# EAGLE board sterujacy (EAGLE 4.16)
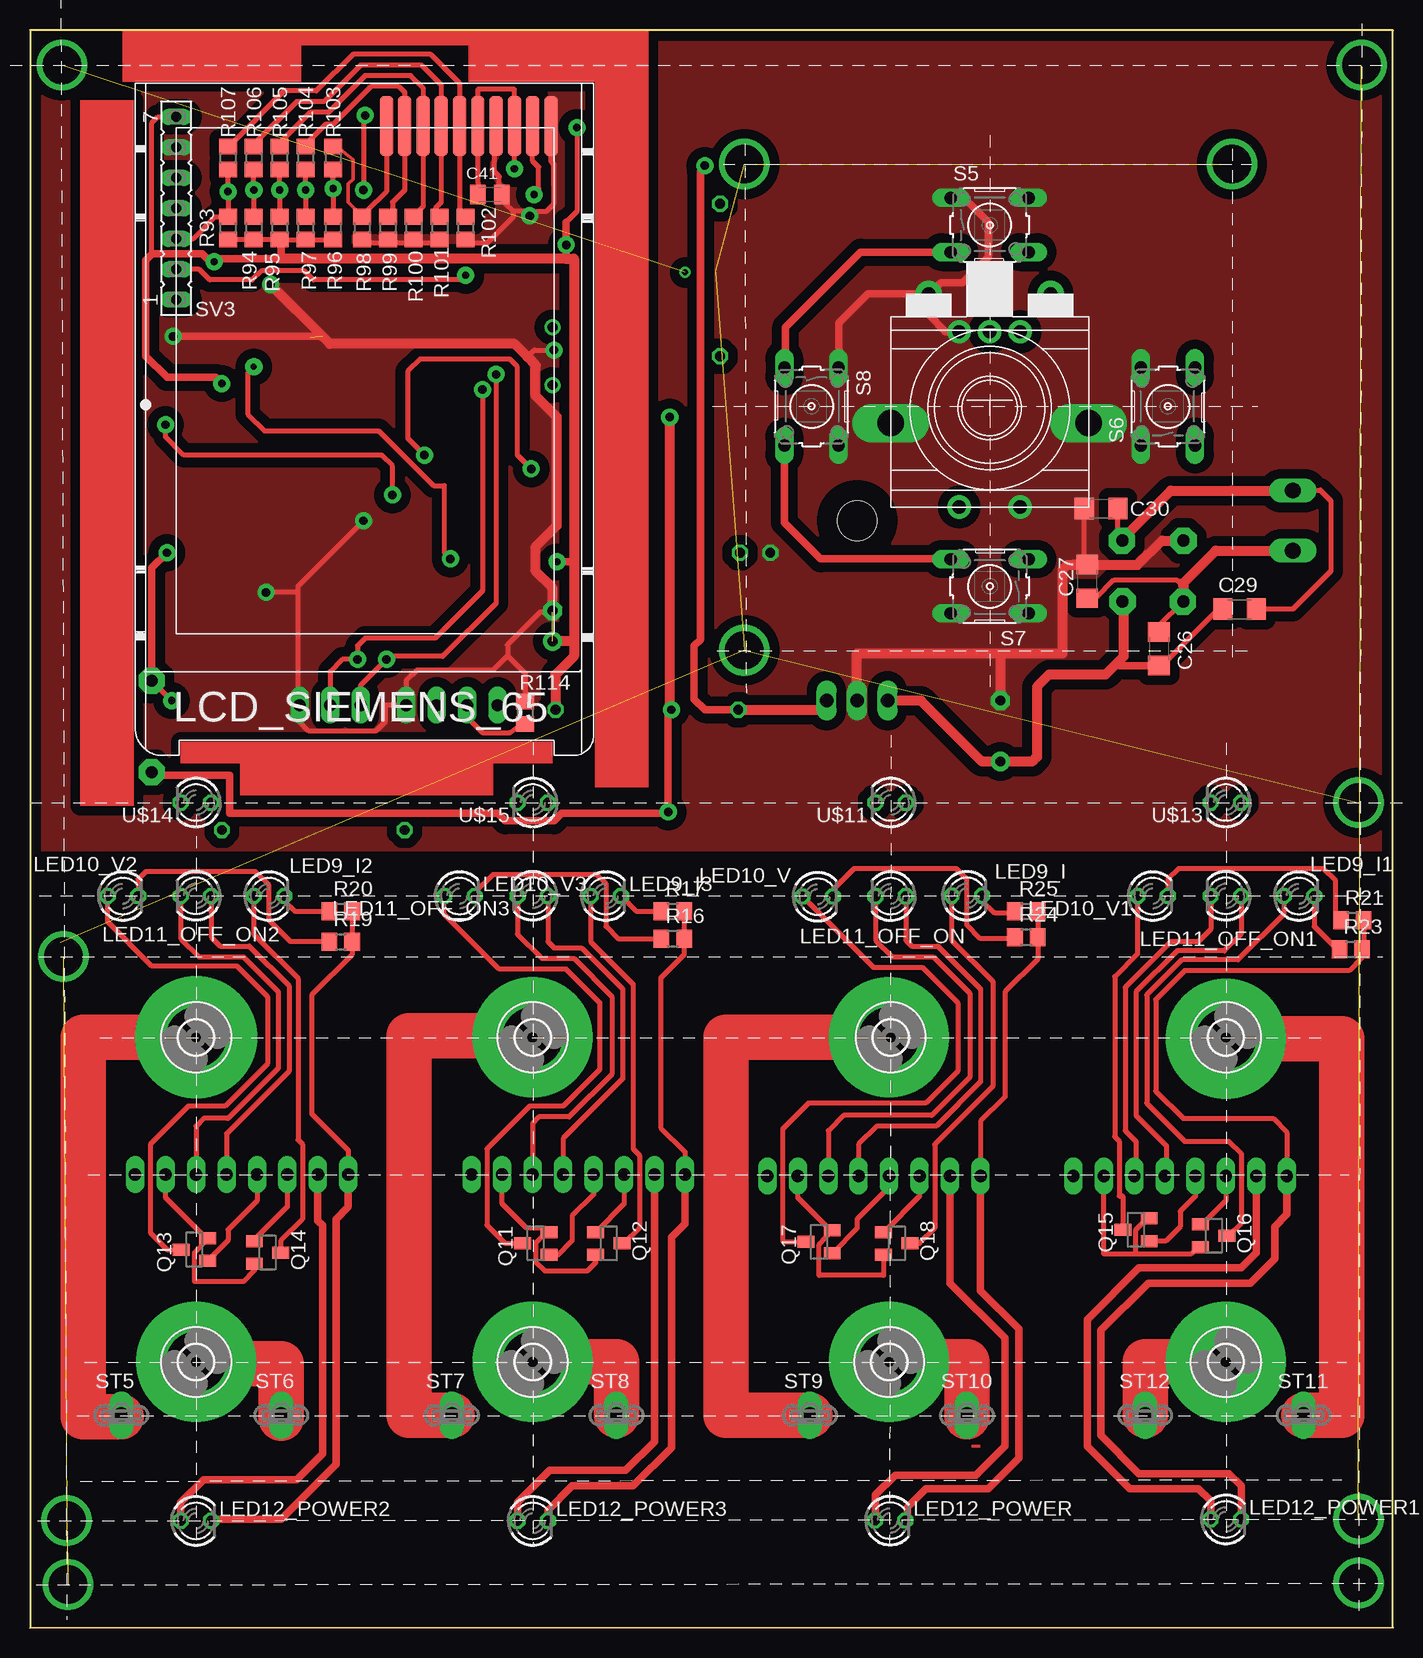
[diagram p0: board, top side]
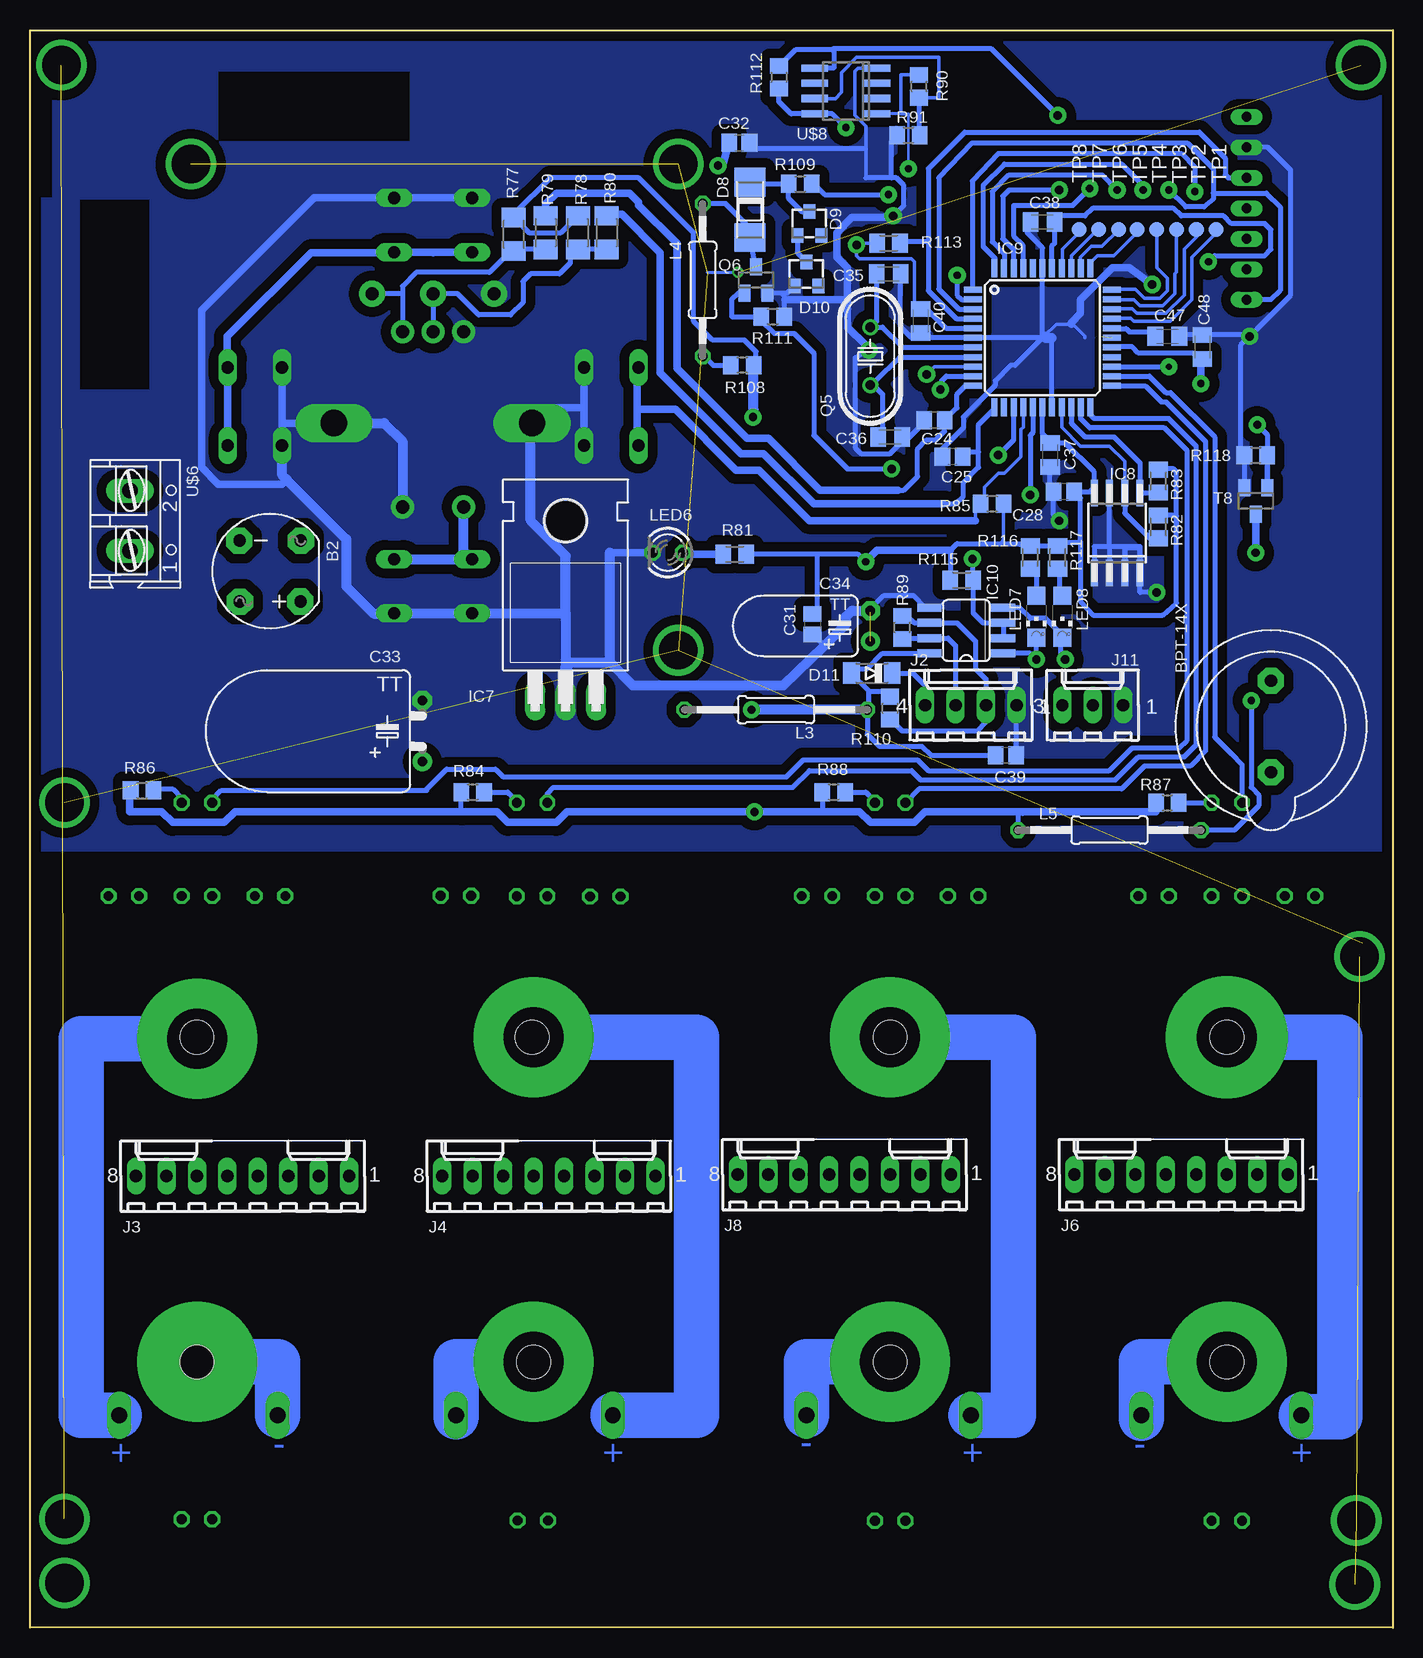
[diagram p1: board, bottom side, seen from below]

Size 113.61 x 133.15 mm. Coordinates in mm from the lower left corner, seen from the top.
Outline: 0,0 113.61,0.05 113.61,133.12 0,133.15 0,0
Copper layers (1*16): Top 0.035mm / dielectric 1.5mm / Bottom 0.035mm
Design rules "default": minimum track width 10mil, minimum drill 20mil, track to track 8mil, track to pad 8mil, pad to pad 8mil, via to via 8mil, smd to smd 8mil, copper to edge 1mil, drill to drill 8mil, minimum pad ring 10mil, minimum via ring 8mil, stop-mask expansion 4mil, vias tented up to drill 0mil, thermal gap 10mil

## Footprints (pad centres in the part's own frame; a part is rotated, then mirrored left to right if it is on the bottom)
RB1A = drill 1.016 round: + -2.54,2.54 | drill 1.016 octagon: - 2.54,-2.54; AC1 2.54,2.54; AC2 -2.54,-2.54
F/HGP = drill 1.016 pad 2.159 octagon: 1 -3.81,0; 2 3.81,0
C0805 = smd 1.3 x 1.5: 1 -0.85,0; 2 0.85,0
C1206 = smd 1.6 x 1.8: 1 -1.4,0; 2 1.4,0
TT5D11L = drill 0.813 pad 1.6 round: + -2.54,0 | drill 0.813 pad 1.6 octagon: - 2.54,0
TT2D5L = drill 0.813 pad 1.6 round: + -1.27,0 | drill 0.813 pad 1.6 octagon: - 1.27,0
C0805K = smd 1.3 x 1.6: 1 -1,0; 2 1,0
SOD106A = smd 2.4 x 2.6: A 2.3,0; K -2.3,0
TO236 = smd 1 x 1.2: A -1,-1; C 0,1; NC 1,-1
MINIMELF = smd 1.4 x 1.8: A 1.7,0; C -1.7,0
2,8 = hole 2.8: 0,0
TO220H = drill 1.118 long: 1 -2.54,-10.16; 2 0,-10.16; 3 2.54,-10.16 | hole 3.302: 0,4.826
SO-08M = smd 0.6 x 2.2: 1 -1.905,-3.33; 2 -0.635,-3.33; 3 0.635,-3.33; 4 1.905,-3.33; 5 1.905,3.33; 6 0.635,3.33; 7 -0.635,3.33; 8 -1.905,3.33
TQFP44 = smd 1.5 x 0.5: 1 -5.8,4; 2 -5.8,3.2; 3 -5.8,2.4; 4 -5.8,1.6; 5 -5.8,0.8; 6 -5.8,0; 7 -5.8,-0.8; 8 -5.8,-1.6; 9 -5.8,-2.4; 10 -5.8,-3.2; 11 -5.8,-4; 23 5.8,-4; 24 5.8,-3.2; 25 5.8,-2.4; 26 5.8,-1.6; 27 5.8,-0.8; 28 5.8,0; 29 5.8,0.8; 30 5.8,1.6; 31 5.8,2.4; 32 5.8,3.2; 33 5.8,4 | smd 0.5 x 1.5: 12 -4,-5.8; 13 -3.2,-5.8; 14 -2.4,-5.8; 15 -1.6,-5.8; 16 -0.8,-5.8; 17 0,-5.8; 18 0.8,-5.8; 19 1.6,-5.8; 20 2.4,-5.8; 21 3.2,-5.8; 22 4,-5.8; 34 4,5.8; 35 3.2,5.8; 36 2.4,5.8; 37 1.6,5.8; 38 0.8,5.8; 39 0,5.8; 40 -0.8,5.8; 41 -1.6,5.8; 42 -2.4,5.8; 43 -3.2,5.8; 44 -4,5.8
SO08 = smd 0.66 x 2.032: 1 -1.905,-3.073; 2 -0.635,-3.073; 3 0.635,-3.073; 4 1.905,-3.073; 5 1.905,3.073; 6 0.635,3.073; 7 -0.635,3.073; 8 -1.905,3.073
6410-04 = drill 1.016 long: 1 3.81,0; 2 1.27,0; 3 -1.27,0; 4 -3.81,0
6410-08 = drill 1.016 long: 1 8.89,0; 2 6.35,0; 3 3.81,0; 4 1.27,0; 5 -1.27,0; 6 -3.81,0; 7 -6.35,0; 8 -8.89,0
6410-03 = drill 1.016 long: 1 2.54,0; 2 0,0; 3 -2.54,0
0207/15@1 = drill 0.813 octagon: 1 -7.62,0; 2 7.62,0
0207/12 = drill 0.813 octagon: 1 -6.35,0; 2 6.35,0
LED3MM = drill 0.813 octagon: A -1.27,0; K 1.27,0
CHIPLED_1206 = smd 1.5 x 1.5: A 0,-1.75; C 0,1.75
HC49U70 = drill 0.813 round: 1 -2.413,0; 2 2.413,0
SOT23 = smd 1 x 1.4: 1 -0.95,-1.1; 2 0.95,-1.1; 3 0,1.1
R0805 = smd 1.3 x 1.5: 1 -0.95,0; 2 0.95,0
M1206 = smd 1.6 x 2: 1 -1.4,0; 2 1.4,0
M0805 = smd 1.3 x 1.6: 1 -0.95,0; 2 0.95,0
B3F-10XX = drill 1.016 long: 1 -3.251,2.261; 2 3.251,2.261; 3 -3.251,-2.261; 4 3.251,-2.261
ST2,8 = drill 1.321 long: 1 0,0
FE07 = drill 0.813 long: 1 -7.62,0; 2 -5.08,0; 3 -2.54,0; 4 0,0; 5 2.54,0; 6 5.08,0; 7 7.62,0
B1,27 = smd 1.27 x 1.27: PP 0,0
ENKODER_PROSTY = drill 1.1 pad 2.184 round: A -5.08,0; B 0,0; C 5.08,0 | drill 1.1 pad 1.93 round: A.A -2.54,3.175; B.B 0,3.175; C.C 2.54,3.175; S1 -2.54,17.78; S2 2.54,17.78 | drill 2.2 pad 3 long: GN -8.255,10.795; GN1 8.255,10.795
AK300/2_MK = drill 1.321 long: 1 -2.515,0; 2 2.489,0
SIEMENS65 = smd 5 x 1.1: 1V8 -21.463,11.938; 2V9 -21.463,8.89; CLK -21.463,5.842; CS -21.463,4.318; DAT -21.463,7.366; GND -21.463,10.414; LED+ -21.463,13.462; LED_GND -21.463,14.986; RESET -21.463,2.794; RS -21.463,1.27
SO08' = smd 0.6 x 2.2: 1 -1.905,-2.6; 2 -0.635,-2.6; 3 0.635,-2.6; 4 1.905,-2.6; 5 1.905,2.6; 6 0.635,2.6; 7 -0.635,2.6; 8 -1.905,2.6

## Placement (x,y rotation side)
B2  B50C1500  [RB1A]  93.59,88.07 180 bottom
BPT-14X  BPT-14X  [F/HGP]  10.15,75.12 90 bottom
C24  1n  [C0805]  38.22,100.65 180 bottom
C25  1n  [C0805]  36.7,97.6 180 bottom
C26  100n  [C1206]  94.1,81.6 270 top
C27  100n  [C1206]  88.13,87.21 90 top
C28  100n  [C0805]  27.43,94.68 180 bottom
C29  100n  [C1206]  100.83,84.9 0 top
C30  100n  [C1206]  89.28,93.28 0 top
C31  100n  [C0805]  48.38,83.63 270 bottom
C32  100n  [C0805]  54.48,123.76 0 bottom
C33  1000u/25V  [TT5D11L]  80.89,74.74 90 bottom
C34  100u  [TT2D5L]  43.56,83.5 90 bottom
C35  15p  [C0805K]  42.03,112.84 180 bottom
C36  15p  [C0805K]  41.91,99.25 180 bottom
C37  100n  [C0805K]  28.57,97.72 270 bottom
C38  100n  [C0805K]  29.2,117.16 0 bottom
C39  100n  [C0805]  32.25,72.71 180 bottom
C40  100n  [C0805K]  39.36,108.9 90 bottom
C41  100n  [C0805K]  38.35,119.44 180 top
C47  1n5  [C0805K]  18.79,107.63 0 bottom
C48  100n  [C0805K]  15.87,106.74 270 bottom
D8  BYS10-45  [SOD106A]  53.59,118.17 270 bottom
D9  6v2  [TO236]  48.64,117.03 0 bottom
D10  6v2  [TO236]  48.89,112.84 0 bottom
D11  BAV103  [MINIMELF]  43.43,79.56 180 bottom
H1  MOUNT-HOLE2.8  [2,8]  13.84,22.16 0 top
H2  MOUNT-HOLE2.8  [2,8]  13.84,49.21 0 top
H3  MOUNT-HOLE2.8  [2,8]  41.91,49.21 0 top
H4  MOUNT-HOLE2.8  [2,8]  41.91,22.16 0 top
H5  MOUNT-HOLE2.8  [2,8]  71.62,22.16 0 top
H6  MOUNT-HOLE2.8  [2,8]  71.75,49.21 0 top
H7  MOUNT-HOLE2.8  [2,8]  99.69,49.21 0 top
H8  MOUNT-HOLE2.8  [2,8]  99.69,22.16 0 top
IC7  7805T  [TO220H]  68.96,87.44 0 bottom
IC8  24C16SM  [SO-08M]  22.98,91.25 0 bottom
IC9  ATMEGA32-16AU  [TQFP44]  29.2,107.5 0 bottom
IC10  SN75176  [SO08]  35.55,83.12 90 bottom
J2  zlacze NS25-W4P  [6410-04]  35.17,76.9 0 bottom
J3  zlacze NS25-W8K  [6410-08]  95.88,37.65 0 bottom
J4  zlacze NS25-W8K  [6410-08]  70.35,37.65 0 bottom
J6  zlacze NS25-W8K  [6410-08]  17.65,37.78 0 bottom
J8  zlacze NS25-W8K  [6410-08]  45.72,37.78 0 bottom
J11  zlacze NS25-W3P  [6410-03]  25.01,76.9 0 bottom
L3  1u  [0207/15@1]  51.43,76.52 180 bottom
L4  220u  [0207/12]  57.53,112.33 90 bottom
L5  1u  [0207/15@1]  23.62,66.48 180 bottom
LED6  LED3mm  [LED3MM]  60.45,89.6 180 bottom
LED7  1206  [CHIPLED_1206]  29.71,84.26 180 bottom
LED8  1206  [CHIPLED_1206]  27.55,84.26 180 bottom
LED9_I  [LED3MM]  78.1,61.02 0 top
LED9_I1  [LED3MM]  105.79,61 0 top
LED9_I2  [LED3MM]  19.93,61 0 top
LED9_I3  [LED3MM]  48,61 0 top
LED10_V  [LED3MM]  65.65,60.95 0 top
LED10_V1  [LED3MM]  93.59,61 0 top
LED10_V2  [LED3MM]  7.74,61 0 top
LED10_V3  [LED3MM]  35.81,61 0 top
LED11_OFF_ON  [LED3MM]  71.75,60.97 180 top
LED11_OFF_ON1  [LED3MM]  99.69,61 180 top
LED11_OFF_ON2  [LED3MM]  13.84,61 180 top
LED11_OFF_ON3  [LED3MM]  41.91,61 180 top
LED12_POWER  [LED3MM]  71.7,8.95 0 top
LED12_POWER1  [LED3MM]  99.69,9.05 0 top
LED12_POWER2  [LED3MM]  13.84,8.93 0 top
LED12_POWER3  [LED3MM]  41.91,8.93 0 top
Q5  16MHz  [HC49U70]  43.56,105.98 90 bottom
Q6  BSS123  [SOT23]  53.08,112.33 0 bottom
Q11  BSS84  [SOT23]  42.16,32.04 90 top
Q12  BSS84  [SOT23]  48.25,32.04 270 top
Q13  BSS84  [SOT23]  13.71,31.53 90 top
Q14  BSS84  [SOT23]  19.81,31.28 270 top
Q15  BSS84  [SOT23]  92.2,33.18 90 top
Q16  BSS84  [SOT23]  98.67,32.68 270 top
Q17  BSS84  [SOT23]  65.78,32.17 90 top
Q18  BSS84  [SOT23]  72.26,32.04 270 top
R16  10k  [R0805]  53.59,57.44 0 top
R17  4k7  [R0805]  53.59,59.73 0 top
R19  4k7  [R0805]  25.9,57.19 0 top
R20  4k7  [R0805]  25.9,59.73 0 top
R21  4k7  [R0805]  110.23,58.96 0 top
R23  4k7  [R0805]  110.1,56.55 0 top
R24  4k7  [R0805]  83.05,57.57 0 top
R25  4k7  [R0805]  83.05,59.73 0 top
R77  10k  [M1206]  73.27,116.14 270 bottom
R78  10k  [M1206]  67.94,116.27 90 bottom
R79  1  [M1206]  70.61,116.27 90 bottom
R80  1  [M1206]  65.53,116.27 90 bottom
R81  680  [M0805]  54.86,89.47 180 bottom
R82  4k7  [M0805]  19.55,91.76 270 bottom
R83  4k7  [M0805]  19.55,95.57 270 bottom
R84  680  [R0805]  76.7,69.66 0 bottom
R85  4k7  [R0805]  33.4,93.66 180 bottom
R86  680  [R0805]  104.26,69.78 0 bottom
R87  680  [R0805]  18.79,68.77 0 bottom
R88  680  [R0805]  46.6,69.66 0 bottom
R89  102  [R0805]  40.89,83.37 90 bottom
R90  470  [R0805]  39.49,128.46 90 bottom
R91  330  [R0805]  40.38,124.39 0 bottom
R93  4k7  [R0805]  16.5,116.65 270 top
R94  4k7  [R0805]  18.66,116.65 270 top
R95  4k7  [R0805]  20.82,116.65 270 top
R96  4k7  [R0805]  25.27,116.65 270 top
R97  4k7  [R0805]  22.98,116.65 270 top
R98  470  [R0805]  27.68,116.65 270 top
R99  470  [R0805]  29.84,116.65 270 top
R100  470  [R0805]  32,116.65 270 top
R101  470  [R0805]  34.16,116.65 270 top
R102  470  [R0805]  36.32,116.65 270 top
R103  330  [R0805]  25.27,122.49 270 top
R104  330  [R0805]  22.98,122.49 270 top
R105  330  [R0805]  20.82,122.49 270 top
R106  330  [R0805]  18.66,122.49 270 top
R107  330  [R0805]  16.5,122.49 270 top
R108  1  [R0805]  54.22,105.22 180 bottom
R109  1  [R0805]  49.4,120.33 0 bottom
R110  510  [R0805]  41.91,76.64 90 bottom
R111  1k  [R0805]  51.68,109.28 0 bottom
R112  100k  [R0805]  51.18,129.22 270 bottom
R113  10k  [M0805]  42.03,115.38 180 bottom
R114  510  [R0805]  41.27,76.26 270 top
R115  4k7  [M0805]  35.94,87.31 180 bottom
R116  680  [M0805]  30.22,89.22 270 bottom
R117  680  [M0805]  27.93,89.22 270 bottom
R118  1M  [R0805]  11.42,97.72 0 bottom
S5  [B3F-10XX]  80,116.9 0 top
S6  [B3F-10XX]  94.86,101.79 90 top
S7  [B3F-10XX]  80,86.8 180 top
S8  [B3F-10XX]  65.15,101.79 270 top
ST5  [ST2,8]  7.61,17.71 0 top
ST6  [ST2,8]  20.95,17.71 0 top
ST7  [ST2,8]  35.17,17.71 0 top
ST8  [ST2,8]  48.89,17.71 0 top
ST9  [ST2,8]  65.02,17.71 0 top
ST10  [ST2,8]  78.1,17.71 0 top
ST11  [ST2,8]  106.17,17.71 0 top
ST12  [ST2,8]  92.96,17.71 0 top
SV3  [FE07]  12.19,118.3 90 top
T8  BSS123  [SOT23]  11.42,93.91 180 bottom
TP1  PTR1B1,27  [B1,27]  14.73,116.52 0 bottom
TP2  PTR1B1,27  [B1,27]  16.38,116.52 0 bottom
TP3  PTR1B1,27  [B1,27]  18.03,116.52 0 bottom
TP4  PTR1B1,27  [B1,27]  19.68,116.52 0 bottom
TP5  PTR1B1,27  [B1,27]  21.33,116.52 0 bottom
TP6  PTR1B1,27  [B1,27]  22.85,116.52 0 bottom
TP7  PTR1B1,27  [B1,27]  24.51,116.52 0 bottom
TP8  PTR1B1,27  [B1,27]  26.16,116.52 0 bottom
U$5  ED16112O  [ENKODER_PROSTY]  80,111.19 180 top
U$6  TB-5.0-P-2P/BL  [AK300/2_MK]  105.28,92.26 270 bottom
U$7  SIEMENS_65/model LS0..  [SIEMENS65]  28.44,103.69 270 top
U$8  LP2951CM-3.0  [SO08']  45.59,128.08 90 bottom
U$11  [LED3MM]  71.75,68.77 180 top
U$13  [LED3MM]  99.69,68.77 180 top
U$14  [LED3MM]  13.84,68.77 180 top
U$15  [LED3MM]  41.91,68.77 180 top

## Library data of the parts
B2 = rectifier
BPT-14X = buzzer
C24-C41 C47 C48 L3-L5 R16 R17 R19-R21 R23-R25 R77-R91 R93-R118 = rcl
D8 = telefunken
D9-D11 = diode
H1-H8 = holes
IC7 U$8 = linear
IC8 = microchip
IC9 = atmel
IC10 = maxim
J2-J4 J6 J8 J11 = con-molex
LED6-LED8 LED9_I LED9_I1-LED9_I3 LED10_V LED10_V1-LED10_V3 LED11_OFF_ON LED11_OFF_ON1-LED11_OFF_ON3 LED12_POWER LED12_POWER1-LED12_POWER3 U$11 U$13-U$15 = led
Q5 = crystal
Q6 Q11-Q18 T8 = transistor-small-signal
S5-S8 = switch-omron
ST5-ST12 = con-rib
SV3 = con-lsta
TP1-TP8 = testpad
U$5 = piher
U$6 = con-ptr500
U$7 = display-lcd

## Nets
0V: B2.- C24.2 C25.2 C27.2 C28.2 C30.1 C31.2 C32.2 C33.- C34.- C35.1 C36.1 C37.2 C38.1 C39.1 C40.1 C41.1 C47.2 C48.1 D10.A IC7.2 IC8.1 IC8.2 IC8.3 IC8.4 IC8.7 IC9.6 IC9.18 IC9.28 IC9.39 IC10.5 J2.1 J11.1 LED6.K Q6.2 R91.1 R98.2 R99.2 R100.2 R101.2 R102.2 R111.2 R114.1 R118.1 S5.1 S5.2 S6.1 S6.2 S7.1 S7.2 S8.1 S8.2 SV3.6 T8.2 U$5.C U$5.C.C U$5.GN U$5.GN1 U$5.S1 U$7.GND U$7.LED_GND U$8.4
+3V3: C41.2 R90.2 U$7.1V8 U$7.2V9 U$8.1
+5V: BPT-14X.1 C28.1 C31.1 C34.+ C37.1 C38.2 C39.2 C40.2 C48.2 D11.A IC8.8 IC9.5 IC9.17 IC9.27 IC9.38 IC10.8 L3.1 L5.2 R77.1 R78.2 R81.1 R82.1 R83.1 R84.1 R85.1 R86.1 R87.1 R88.1 R93.2 R94.2 R95.2 R96.2 R97.2 R108.1 R110.2 R112.2 R113.2 R115.2 R116.1 R117.1 SV3.7 U$8.8
+_1: ST5.1
+_2: ST7.1
+_3: ST9.1
+_4: ST11.1
-_1: ST6.1
-_2: ST8.1
-_3: ST10.1
-_4: ST12.1
A_S: IC10.6 J2.2 R89.2 R110.1
B_S: IC10.7 J2.3 R89.1 R114.2
CS_LCD: IC9.44 R95.1 R105.2
EN_A: C24.1 IC9.11 R79.2
EN_B: C25.1 IC9.12 R80.2
ERROR_ZAS: IC9.42 R112.1 U$8.5
GND_M: J8.8 LED12_POWER3.K R16.2 R17.2
GND_M1: J6.8 LED12_POWER2.K R19.2 R20.2
GND_M2: J3.8 LED12_POWER1.K R21.2 R23.2
GND_M3: J4.8 LED12_POWER.K R24.2 R25.2
K1: IC9.15 R85.2 S5.3 S5.4 S6.3 S6.4 S7.3 S7.4 S8.3 S8.4 U$5.S2
KIERUNEK_RS485: IC9.25 IC10.2 IC10.3 R115.1
LED1: IC9.21 U$13.K
LED2: IC9.22 U$11.K
LED3: IC9.23 U$15.K
LED4: IC9.24 U$14.K
MISO_G: IC9.2 SV3.2
MOSI_G: IC9.1 R93.1 R107.2 SV3.3
N$9: LED10_V.K R24.1
N$13: IC9.30 TP1.PP
N$15: IC9.31 TP2.PP
N$18: IC9.32 TP3.PP
N$20: LED9_I.K R25.1
N$21: D11.C J2.4
N$24: LED9_I.A Q18.3
N$26: IC9.33 TP4.PP
N$27: IC9.34 TP5.PP
N$29: IC9.35 TP6.PP
N$30: IC9.36 TP7.PP
N$32: IC9.37 TP8.PP
N$46: J4.7 LED12_POWER.A
N$53: J4.6 Q18.1
N$58: C47.1 IC9.29
N$70: J4.3 LED11_OFF_ON.K
N$71: J4.4 LED11_OFF_ON.A
N$72: LED10_V1.A Q15.3
N$73: LED10_V1.K R21.1
N$74: LED9_I1.K R23.1
N$75: J3.7 LED12_POWER1.A
N$76: LED9_I1.A Q16.3
N$77: J3.3 LED11_OFF_ON1.K
N$78: J3.4 LED11_OFF_ON1.A
N$79: R98.1 R103.1 U$7.RS
N$80: C35.2 IC9.7 Q5.2
N$81: LED10_V2.A Q13.3
N$82: LED10_V2.K R19.1
N$83: LED9_I2.K R20.1
N$84: J6.7 LED12_POWER2.A
N$85: C36.2 IC9.8 Q5.1
N$86: LED7.A R116.2
N$87: LED8.A R117.2
N$89: R84.2 U$11.A
N$90: R100.1 R105.1 U$7.CS
N$91: R101.1 R106.1 U$7.CLK
N$92: R86.2 U$13.A
N$93: R109.2 U$7.LED+
N$94: R90.1 R91.2 U$8.7
N$95: C32.1 IC7.3 L3.2
N$96: LED6.A R81.2
N$97: B2.AC2 C29.2 C30.2 U$6.1
N$101: LED9_I2.A Q14.3
N$103: J6.3 LED11_OFF_ON2.K
N$104: R87.2 U$14.A
N$105: D8.A L4.2 Q6.3
N$106: D9.A D10.C
N$107: D8.K D9.C R109.1
N$108: L4.1 R108.2
N$109: B2.AC1 C26.1 C27.1 U$6.2
N$110: B2.+ C26.2 C29.1 C33.+ IC7.1
N$111: R99.1 R104.1 U$7.RESET
N$113: R102.1 R107.1 U$7.DAT
N$114: J6.4 LED11_OFF_ON2.A
N$116: LED9_I3.K R17.1
N$117: LED9_I3.A Q12.3
N$118: J8.6 Q12.1
N$119: J8.7 LED12_POWER3.A
N$120: R88.2 U$15.A
N$121: J8.5 Q11.1
N$122: J8.3 LED11_OFF_ON3.K
N$123: J8.4 LED11_OFF_ON3.A
N$129: J8.2 Q11.2 Q12.2
N$130: BPT-14X.2 L5.1 T8.3
N$131: LED10_V3.A Q11.3
N$132: LED10_V3.K R16.1
N$133: J6.6 Q14.1
N$134: J6.5 Q13.1
N$135: J6.2 Q13.2 Q14.2
N$136: J3.6 Q16.1
N$137: J3.5 Q15.1
N$138: J3.2 Q15.2 Q16.2
N$139: J4.5 Q17.1
N$140: J4.2 Q17.2 Q18.2
N$141: LED10_V.A Q17.3
N$151: R77.2 R79.1 U$5.A U$5.A.A
N$152: R78.1 R80.1 U$5.B U$5.B.B
PIK: IC9.16 R118.2 T8.1
PWM_LCD: IC9.14 Q6.1 R111.1
RESET_LCD: IC9.43 R97.1 R104.2
RS_LCD: IC9.41 R96.1 R103.2
RST_G: IC9.4 R113.1 SV3.5
RXD_G: IC9.9 IC10.1 J11.3 LED7.C
SCK_G: IC9.3 R94.1 R106.2 SV3.1
SCL: IC8.6 IC9.19 R82.2
SDA: IC8.5 IC9.20 R83.2
SHUTDOWN: U$8.3
TXD_G: IC9.10 IC10.4 J11.2 LED8.C

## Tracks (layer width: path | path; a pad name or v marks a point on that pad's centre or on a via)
0V  (via drill 0.7 pad 1.42)  (1 unrouted)
  Top 0.152: 27.68,115.45 27.6,115.45 27.6,115.5 29.2,115.5
  Top 0.406: 40.25,118.04 39.62,118.68 39.62,119.44 39.11,119.95 39.11,120.97 38.73,121.35 38.73,124.78 38.98,125.03 U$7.GND | 41.65,118.04 40.25,118.04 | 41.65,118.04 43.05,118.04 43.68,118.68 43.68,121.98 43.43,122.24 U$7.LED_GND | 27.87,115.7 28.19,115.38 29.71,115.38 29.84,115.5 R99.2 30.03,115.7 30.35,115.38 31.74,115.38 32,115.63 R100.2 32.19,115.7 32.51,115.38 33.9,115.38 34.16,115.63 R101.2 34.35,115.7 34.67,115.38 | R102.2 36.32,115.63 36.06,115.38 38.09,115.38 40.25,117.54 40.25,118.04 | v41.65,117.66 41.65,118.04 | 39.81,81.02 38.6,79.82 32.25,79.82 31.36,78.93 J2.1 29.59,76.9 29.59,75.5 28.82,74.74 23.24,74.74 22.47,75.5 J11.1 22.35,77.02 22.35,86.29 | v27.81,92.26 22.35,86.8 22.35,86.29 | 22.35,86.29 v19.68,86.29 | 87.19,88.61 C27.2 87.88,88.86 C30.1 | R114.1 41.27,79.56 39.81,81.02 | 43.3,84.64 43.43,84.77 C34.- 43.43,84.64 42.54,84.64 39.81,81.91 39.81,81.02 | 43.68,84.77 43.56,84.64 | 43.43,106.49 42.03,106.49 41.46,105.92
  Top 0.61: 43.43,106.49 v43.68,106.49 | 24.38,107.63 v11.93,107.63 | S8.1 67.41,105.07 67.43,105.09 67.43,108.77 69.84,111.19 U$5.C | S5.1 77.87,119.16 79.88,117.16 79.88,114.23 77.72,112.08 75.94,112.08 75.05,111.19 U$5.C | U$5.C.C 76.32,108.01 74.92,109.41 U$5.C
  Top 0.813: IC7.2 68.96,81.21 80.89,81.21 | 80.89,81.21 86.1,81.21 86.1,88.2 86.48,88.58 86.99,88.58 | v20.06,111.95 24.38,107.63 25.01,107 40.38,107 41.46,105.92 42.16,105.22 42.16,102.68 43.94,100.9 43.94,91.88 42.16,90.1 42.16,88.07 43.56,86.68 C34.- | 86.99,88.58 92.32,88.58 94.36,90.61 B2.- | 86.99,88.58 87.02,88.61 87.19,88.61 | 80.89,81.21 C33.-
  Bottom 0.305: 25.65,107.5 25.65,107.63 26.66,108.65 26.79,108.65 28.06,108.65 29.08,107.63 | U$8.4 44.57,129.98 44.83,129.73 44.83,126.05 43.94,125.16 43.94,123.25 43.94,120.84 | D10.A 50.67,111.06 50.67,110.68
  Bottom 0.406: 29.2,107.5 IC9.39 29.2,115 30.47,116.27 30.47,116.65 30.2,116.92 C38.1 | IC9.28 23.36,107.5 | 29.2,107.5 28.44,107.5 28.44,101.7 IC9.18 | 29.2,107.5 IC9.6 39.87,107.5 | 50.8,111.23 50.5,111.23 D10.A | 50.8,111.23 Q6.2 | 50.8,111.23 50.8,111.06 50.73,111 R111.2 | v41.65,117.66 40.76,118.55 40.76,120.2 41.4,120.84 41.78,120.84 | T8.2 12.37,95.12 12.31,95.18 12.37,95.25 R118.1 12.69,97.72 12.69,106.87 v11.93,107.63 | 24.89,87.82 IC8.1 24.89,90.1 23.62,90.1 | 21.08,89.98 IC8.4 | 21.08,89.98 21.08,90.1 22.35,90.1 | 22.35,90.1 23.62,90.1 | 22.35,90.1 IC8.3 22.35,89.98 21.08,89.98 | 23.62,90.1 IC8.2 | 23.62,90.1 IC8.7 | 28.28,94.76 C28.2 | C37.2 28.57,95.06 28.28,94.76 | 38.98,100.52 39.07,100.61 C24.2 | C36.1 40.25,99.25 38.98,100.52 | C25.2 37.55,98.27 35.81,100.01 35.81,100.9 33.14,103.57 33.14,103.95 31.87,105.22 31.49,105.22 29.08,107.63 | 38.98,100.52 40.38,99.12 40.63,99.12 41.91,97.85 44.32,97.85 44.83,98.36 44.83,105.85 v43.68,106.49 | 41.78,120.84 43.94,120.84 | SV3.6 10.41,123.38 8.5,121.47 8.5,111.06 v11.93,107.63 | 28.28,94.76 28.28,92.73 v27.81,92.26 | 21.08,89.98 21.08,86.29 v19.68,86.29 | C32.2 53.12,123.25 43.94,123.25 | R91.1 41.78,123.95 41.78,120.84 | 47.37,81.86 47.37,81.85 | 47.37,81.86 | C31.2 48.29,82.78 47.37,81.86 | IC10.5 38.98,85.02 40,86.04 42.41,86.04 43.56,84.9 C34.- | C39.1 31.4,76.86 J2.1 | 39.87,107.5 40.13,107.5 41.03,108.41 C35.1 | C40.1 39.36,107.88 39.75,107.5 39.87,107.5 | C47.2 17.77,107.5 17.54,107.74 C48.1 12.17,107.74 12.06,107.63 v11.93,107.63
  Bottom 0.61: S7.1 83.2,84.54 83.18,84.52 83.16,84.54 S7.2 | 83.26,119.11 83.31,119.06 | 83.26,119.11 S5.2 | 83.26,119.11 83.2,119.16 S5.1 89.94,119.16 99.31,109.79 99.31,96.71 97.91,95.31 92.58,95.31 92.2,95.69 | v43.68,106.49 43.94,106.87 45.46,108.39 45.46,110.68 | 45.46,110.68 45.46,113.35 46.35,114.23 46.35,116.27 45.08,117.54 41.78,117.54 v41.65,117.66 | 45.46,110.68 50.67,110.68 | v20.06,111.95 21.97,113.35 23.36,113.35 26.03,110.68 26.03,109.54 26.79,108.77 26.79,108.65 | 67.51,98.54 67.43,98.49 | 67.51,98.54 S8.2 | 67.41,101.66 67.41,98.64 67.51,98.54 | S8.1 67.41,101.66 | 71.62,100.39 70.35,101.66 67.41,101.66 | 65.27,89.6 LED6.K | 92.58,98.49 92.58,98.54 | U$5.GN 92.58,100.39 92.58,98.87 | 92.58,98.54 92.58,98.87 | 92.58,98.54 S6.1 | S6.2 92.58,105.04 92.58,98.87
  Bottom 0.813: 28.44,107.5 28.95,107.5 29.08,107.63 | 65.27,80.45 63.37,78.55 50.8,78.55 47.37,81.86 46.99,82.23 45.59,83.63 45.59,84.26 45.08,84.77 C34.- | 65.27,80.45 68.7,80.45 68.96,80.2 68.96,77.53 68.83,77.4 | 65.27,80.45 65.27,89.6 | 71.88,100.26 71.88,92.26 68.96,89.34 68.96,84.52 | 68.96,84.52 68.96,80.45 68.83,80.33 68.83,77.4 | 68.83,77.4 IC7.2 | 68.96,84.52 69.08,84.52 69.11,84.54 S7.1 83.28,84.54 83.31,84.52 84.96,84.52 87.24,86.8 87.24,90.74 92.2,95.69 92.58,96.07 92.58,98.49 92.6,98.51 S6.1 | U$5.S1 82.55,98.87 84.07,100.39 U$5.GN
  pour Bottom: 63.75,95.82 74.29,95.82 74.29,79.82 74.16,79.69 63.62,79.69 63.62,95.69
  pour Bottom: 24.89,111.69 33.4,111.69 33.4,103.44 24.89,103.44
  pour Bottom (isolate 0.813, rank 6, no thermals): -0.01,133.16 97.91,133.16 97.91,129.86 81.78,129.86 81.78,123.76 98.04,123.76 98.04,133.16 111.63,133.16 111.63,119.19 103.5,119.19 103.5,103.06 109.6,103.06 109.6,119.06 113.66,119.06 113.66,64.83 -0.01,64.83
  pour Top (isolate 0.813, rank 6, no thermals): -0.01,133.16 -0.01,64.83 113.66,64.83 113.66,133.16
1  (via drill 0.51, 3.2 pad 4)  (6 unrouted)
  Bottom 0.254: 57.14,112.96 v54.6,112.96
  other vias: 2.66,130.24 110.74,68.77 100.2,121.98 59.56,121.98 59.56,81.47
+3V3  (via drill 0.6 pad 1.42)
  Top 0.406: C41.2 37.35,120.44 37.33,120.46 U$7.2V9 37.33,128.2 40.38,128.2 U$7.1V8 v40.38,121.6
  Bottom 0.203: 40.38,126.17 v40.38,121.6
  Bottom 0.254: 40.38,126.17 41.02,126.17 U$8.1
  Bottom 0.305: R90.2 41.02,129.41 41.02,126.17
  Bottom 0.406: U$8.1 43.05,126.17
+5V  (via drill 0.6 pad 1.42, 0.7 pad 1.42)  (1 unrouted)
  Top 0.406: 25.65,115.63 25.52,115.63 25.46,115.7 R96.2 25.27,115.63 | 25.27,115.63 25.14,115.5 | 25.27,115.63 25.27,115.5 25.07,115.7 R97.2 22.92,115.7 22.85,115.63 22.79,115.7 R95.2 | R93.2 18.47,115.7 18.54,115.63 18.6,115.7 R94.2 R95.2 | SV3.7 10.66,125.92 10.15,125.41 10.15,114.62 10.22,114.55 | R95.2 20.88,115.7 20.95,115.63 | v15.36,113.85 15.36,113.98 15.49,114.11 | 20.82,114.11 20.95,114.23 | 44.7,117.16 45.59,118.04 v45.59,125.03
  Top 0.61: BPT-14X.1 10.15,71.05 16.63,71.05 16.63,67.88 38.98,67.88 39.62,67.24 43.68,67.24 44.32,67.88 53.08,67.88 v53.21,68.01 53.21,76.13 53.33,76.52 v53.46,76.52 | v16,103.69 15.49,104.2 11.42,104.2 9.65,105.98 9.65,113.98 10.22,114.55 10.31,114.51 14.37,114.51 14.78,114.11 15.49,114.11 20.82,114.11 | 45.33,88.83 v43.94,88.83 | 20.95,114.23 20.95,115.63 | 44.57,114.11 44.57,114.23 44.7,114.36 v44.7,115.25 44.7,117.16
  Top 0.813: 53.33,76.52 v53.33,100.9 | L3.1 43.81,79.44 45.33,80.96 45.33,82.23 | 45.33,82.23 C34.+ | 45.33,82.23 45.33,88.83 45.33,114.11 44.57,114.11 20.82,114.11
  Bottom 0.305: R88.1 47.55,68.07 47.62,68.01 | R85.1 32.45,90.67 32.63,90.49 32.63,90.36 | C40.2 39.87,110.17 39.87,113.85 40.13,114.11 44.44,114.11 44.7,114.36 v44.7,115.25 44.57,115.38 R113.2
  Bottom 0.406: IC9.17 29.2,99.5 28.81,99.11 C37.1 27.28,98.72 24.89,96.33 IC8.8 | 28.44,113.22 28.4,113.26 IC9.38 28.4,113.43 28.44,113.47 28.44,115.12 28.2,115.36 28.2,117.01 28.06,117.16 C38.2 28.19,117.16 27.81,117.54 27.81,117.66 25.65,117.66 25.01,118.3 18.28,118.3 17.65,117.66 14.09,117.66 13.46,117.03 10.66,117.03 10.15,116.52 10.15,114.87 10.66,114.36 14.85,114.36 v15.36,113.85 | R78.2 69.08,116.52 69.34,116.27 72,116.27 R77.1 73.27,117.79 70.23,120.84 62.86,120.84 58.29,116.27 58.29,108.9 56.7,107.32 54.04,107.32 53.08,106.36 53.08,105.47 53.27,105.28 R108.1 | R83.1 19.11,96.52 19.04,96.58 18.28,96.58 18.03,96.33 18.03,92.64 | R82.1 18.34,92.71 18.28,92.64 18.03,92.64 | IC8.8 24.89,94.68 | IC8.8 24.91,94.58 25.14,94.8 25.27,94.68 C28.1 26.58,94.59 26.16,94.17 26.03,94.17 26.03,90.49 | 18.03,92.01 18.03,92.14 | 18.03,92.01 18.03,92.64 | 23.32,106.74 23.49,106.74 | 23.32,106.74 IC9.27 | 23.32,106.74 21.71,106.74 21.2,106.23 16.63,106.23 16.12,105.73 16.11,105.74 C48.2 15.98,105.74 16.12,105.6 | 18.03,92.01 18.03,85.41 19.17,84.39 25.01,84.39 26.03,85.53 26.03,90.49 | 30.73,68.01 30.86,67.88 | 31.24,68.01 L5.2 | R84.1 77.65,68.01 77.59,68.01 | IC10.8 42.54,81.21 43.81,79.94 44.83,79.94 45.13,79.64 D11.A 45.21,79.56 43.68,78.04 | 26.03,90.49 27.43,90.49 27.75,90.17 R117.1 | R88.1 47.55,68.13 47.49,68.13 47.49,68.01 | 32.1,90.33 30.29,90.17 R116.1 | R117.1 27.93,90.23 | R117.1 27.93,90.1 | R116.1 R117.1 | C39.2 38.48,72.71 39.24,73.47 42.79,73.47 43.81,74.48 L3.1 | R110.2 41.97,77.59 42.41,78.04 43.68,78.04 | R116.1 30.22,90.23 30.35,90.36 32.63,90.36 36.32,90.36 36.89,89.79
  Bottom 0.406: 48.38,84.65 C31.1 48.38,84.52 48,84.9 48,89.47 | R115.2 36.89,89.66 36.95,89.72 36.95,89.79 | 43.68,78.04 43.68,76.64 L3.1 | L3.1 43.81,76.64 | 48,89.47 R81.1 | 43.56,84.64 43.81,84.9 | IC9.5 37.24,108.3 38.86,109.92 C40.2 | 48,89.47 44.57,89.47 v43.94,88.83 | R112.2 51.18,127.19 50.16,126.17 U$8.8 46.73,126.17 v45.59,125.03
  Bottom 0.61: R86.1 105.21,69.66 105.28,69.66 105.28,68.01 102.61,68.01 101.72,67.12 97.4,67.12 96.51,68.01 77.59,68.01 74.67,68.01 73.78,67.12 69.72,67.12 68.83,68.01 v53.21,68.01 47.62,68.01 47.49,68.01 44.44,68.01 43.56,67.12 39.87,67.12 38.98,68.01 31.24,68.01 30.73,68.01 19.74,68.01 R87.1 | C48.2 15.89,105.74 16,105.85 v16,103.69 | 36.89,89.79 36.95,89.79 42.98,89.79 v43.94,88.83
  Bottom 0.813: R108.1 53.27,101.47 v53.33,100.9 | L3.1 v53.46,76.52
+_1  (via drill 5 pad 10.16)
  Top 3.81: v13.84,49.21 4.44,49.21 4.44,17.59 7.61,17.59
  Bottom 3.81: v13.84,49.21 4.44,49.21 4.44,17.59 7.49,17.59 7.49,17.71 ST5.1
+_2  (via drill 5 pad 10)
  Top 3.81: 41.91,49.34 31.62,49.34 31.62,17.71 ST7.1
  Bottom 3.81: ST7.1 31.62,17.71 31.62,49.21 v41.91,49.21 41.91,49.08
+_3  (via drill 5 pad 10)
  Top 3.81: 71.75,49.21 58.03,49.21 58.03,17.71 ST9.1
  Bottom 3.81: ST9.1 58.03,17.71 58.03,49.21 v71.62,49.21
+_4  (via drill 5 pad 10)
  Top 3.81: v99.69,49.08 109.34,49.08 109.34,17.71 ST11.1
  Bottom 3.81: v99.69,49.08 109.34,49.08 109.34,17.71 ST11.1
-_1  (via drill 5 pad 10)
  Top 0.254: 20.95,18.98 21.58,18.98 ST6.1
  Top 3.81: 13.84,22.03 20.95,22.03 20.95,18.98 ST6.1 20.95,17.46
  Bottom 3.81: 13.46,22.16 v13.84,22.16 20.95,22.16 ST6.1 20.95,17.46
-_2  (via drill 5 pad 10)
  Top 3.81: v41.91,22.16 48.89,22.16 ST8.1
  Bottom 3.81: v41.91,22.16 48.89,22.16 ST8.1
-_3  (via drill 5 pad 10)
  Top 3.81: v71.62,22.16 78.1,22.16 78.1,17.59
  Bottom 3.81: 78.1,17.59 ST10.1 78.1,22.16 v71.62,22.16
-_4  (via drill 1 pad 10)
  Top 3.81: v99.69,22.16 92.96,22.16 ST12.1
  Bottom 3.81: v99.69,22.16 92.96,22.16 ST12.1
A_S
  Bottom 0.406: R89.2 40.44,84.32 39.87,83.75 IC10.6 36.32,83.75 34.79,82.23 34.79,79.94 33.9,79.06 J2.2 33.9,75.5 34.67,74.74 40.89,74.74 41.91,75.75 R110.1
B_S
  Top 0.406: R114.2 41.31,75.54 40,74.61 37.71,74.61 36.44,75.88 J2.3 36.44,77.02
  Bottom 0.406: J2.3 36.44,81.85 37.08,82.48 IC10.7 40.25,82.48 40.31,82.42 R89.1
CS_LCD  (via drill 0.6 pad 1.42)
  Top 0.406: R105.2 v20.82,119.82 R95.1
  Bottom 0.406: v20.82,119.82 20.82,120.2 22.6,121.98 32.38,121.98 34.16,120.2 34.16,115.12 33.17,114.13 33.17,113.47 33.2,113.44 IC9.44
EN_A
  Bottom 0.406: IC9.11 35.62,103.5 36.32,102.8 36.32,101.66 37.33,100.65 C24.1 37.37,99.72 38.09,98.99 38.86,98.99 39.62,98.23 39.62,95.95 40.76,94.8 41.27,94.8
  Bottom 0.61: R79.2 70.61,118.68 69.72,119.57 63.62,119.57 62.86,118.81 62.86,118.55 59.68,115.38 59.68,104.96 53.84,99.12 52.06,99.12 47.75,94.8 41.27,94.8
EN_B
  Bottom 0.406: IC9.12 33.2,101.6 34.54,100.26 34.54,97.98 | 34.54,97.98 34.54,96.71 35.81,95.44 35.81,94.3 36.44,93.66 37.46,93.66 | C25.1 35.81,97.6 35.43,97.98 34.54,97.98
  Bottom 0.61: 37.46,93.66 48.25,93.66 52.45,97.85 54.35,97.85 61.08,104.58 61.08,114.62 64.26,117.79 65.27,117.79 65.4,117.67 R80.2
ERROR_ZAS  (via drill 0.7 pad 1.42)
  Top 0.406: v27.81,119.82 27.81,125.92 v27.93,126.05
  Bottom 0.406: 46.6,131.63 33.52,131.63 v27.93,126.05 | 46.6,131.63 46.6,129.98 U$8.5 | 31.62,113.32 IC9.42 31.6,113.33 31.62,113.35 31.62,114.87 32.51,115.76 32.51,119.31 32,119.82 v27.81,119.82 | R112.1 51.11,130.17 49.78,131.51 46.73,131.51 46.6,131.63
GND_M
  Top 0.406: R17.2 R16.2 | R16.2 54.54,57.25 54.6,57.19 | R16.2 54.54,56.1 52.57,54.14 52.57,41.69 54.6,39.66 J8.8
  Top 0.61: J8.8 54.6,33.69 53.46,32.55 53.46,15.02 50.29,11.85 45.21,11.85 43.17,9.82 LED12_POWER3.K
GND_M1
  Top 0.406: R20.2 R19.2 | R19.2 26.85,57.12 26.79,57.06 | R19.2 26.85,56.1 23.49,52.74 23.49,42.84 26.54,39.79 26.54,38.01 26.66,37.88 26.56,37.78 J6.8
  Top 0.61: J6.8 26.54,35.09 25.52,34.07 25.52,13.63 20.95,9.05 15.23,9.05 LED12_POWER2.K
GND_M2
  Top 0.406: 111.18,56.36 111.05,56.49 R23.2 | 111.18,56.36 R21.2 111.18,56.49 110.99,56.3 110.99,55.79 109.98,54.77 96.26,54.77 93.85,52.36 93.85,44.74 96.13,42.45 103.63,42.45 104.77,41.31 J3.8 | 111.18,56.36 111.37,56.17
  Top 0.61: J3.8 104.77,34.45 103.75,33.44 103.75,30.77 101.72,28.74 93.21,28.74 89.28,24.8 89.28,16.04 92.45,12.86 99.94,12.86 100.96,11.85 LED12_POWER1.K
GND_M3
  Top 0.406: R25.2 84,57.63 83.94,57.57 R24.2 84,55.72 81.28,53 81.28,44.23 79.24,42.2 J4.8 79.24,37.5
  Top 0.61: 79.24,37.5 79.24,28.1 82.42,24.93 82.42,14.13 79.88,11.59 74.67,11.59 73.15,10.07 73.15,9.18 73.27,9.05 73.17,8.95 LED12_POWER.K
K1
  Top 0.61: S8.4 62.88,92.11 65.91,89.09 76.96,89.09 76.93,89.06 S7.4 | S5.3 69.23,114.64 62.99,108.39 62.99,105.09 62.94,105.04 S8.3
  Bottom 0.305: IC9.15 30.8,100.06 30.98,99.88 30.98,97.6 32.38,96.2 32.89,96.2 34.03,95.06 34.03,93.91 34.28,93.66 | 34.28,93.66 R85.2 | 34.79,92.26 34.79,93.15 34.28,93.66
  Bottom 0.61: 83.28,114.64 S5.4 | 83.28,114.64 S5.3 79.98,114.64 80,114.62 | 83.28,114.64 83.31,114.62 90.16,114.62 97.15,107.63 97.15,105.09 97.12,105.07 S6.4 97.12,98.64 97.15,98.61 97.12,98.59 S6.3 | 34.79,92.26 48.64,92.26 52.83,96.45 54.73,96.45 59.81,101.53 62.99,101.53 | S8.4 63.14,98.59 62.99,98.61 62.99,101.53 | S8.3 63.16,105.04 63.24,104.96 62.99,104.71 62.99,101.53
  Bottom 0.813: U$5.S2 77.47,89.72 76.81,89.06 S7.4 76.93,89.06 76.96,89.09 76.98,89.06 S7.3
KIERUNEK_RS485  (via drill 0.5 pad 1.42, 0.7 pad 1.42)
  Top 0.406: v35.05,89.09 34.54,89.6 34.54,95.18 33.65,95.18 29.08,99.76 19.55,99.76 18.16,101.15 18.16,104.58 v18.66,105.09
  Bottom 0.406: IC10.2 32.48,82.59 32.51,82.61 32.48,82.64 IC10.3 34.16,83.75 34.99,84.58 R115.1 35.05,87.31 v35.05,89.09 | IC9.25 23.38,105.1 23.36,105.09 v18.66,105.09
LED1
  Bottom 0.406: U$13.K 98.42,69.02 97.66,69.78 80.64,69.78 | 80.64,69.78 80.51,69.78 | IC9.21 26,100.75 25.27,100.01 19.04,100.01 17.14,98.11 17.14,73.98 17.77,73.34 21.71,73.34 23.62,71.44 38.73,71.44 39.62,72.32 49.14,72.32 50.54,70.93 74.16,70.93 74.8,71.56 78.86,71.56 80.64,69.78
LED2
  Bottom 0.406: IC9.22 25.2,101.09 24.89,100.77 18.66,100.77 16.38,98.49 16.38,73.59 17.39,72.58 21.2,72.58 23.11,70.67 39.36,70.67 40.13,71.44 48.64,71.44 50.03,70.04 69.97,70.04 70.48,69.53 U$11.K
LED3
  Bottom 0.406: IC9.23 20.63,103.5 19.3,102.17 18.92,102.17 15.62,98.87 15.62,73.09 16.89,71.82 20.7,71.82 22.6,69.91 39.49,69.91 U$15.K
LED4
  Bottom 0.406: 13.46,72.83 12.57,71.94 U$14.K | 13.46,72.83 13.71,73.09 | IC9.24 20.29,104.3 18.92,102.93 18.54,102.93 14.85,99.25 14.85,74.23 13.46,72.83
MISO_G  (via drill 0.6 pad 1.42)
  Top 0.406: SV3.2 14.09,113.22 14.98,112.33 18.54,112.33 19.3,113.09 22.85,113.09 23.62,112.33 36.32,112.33 v36.32,112.71
  Bottom 0.406: v36.32,112.71 36.32,111.06 35.94,110.68 35.05,110.68 34.95,110.7 | 34.95,110.7 34.92,110.68 | 34.95,110.7 IC9.2
MOSI_G  (via drill 0.6 pad 1.42)
  Top 0.406: R93.1 16.5,117.54 | R93.1 v16.5,119.7 R107.2 | SV3.3 13.58,115.76 15.36,117.54 16.38,117.54 16.44,117.6 R93.1
  Bottom 0.406: IC9.1 34.73,111.5 35.05,111.57 35.05,120.58 32.89,122.87 17.65,122.87 16.5,121.73 v16.5,119.7
N$9
  Top 0.406: LED10_V.K 66.92,61.5 68.7,63.28 77.21,63.28 78.1,62.39 78.1,58.58 79.24,57.44 81.91,57.44 82.04,57.57 R24.1
N$13
  Bottom 0.305: TP1.PP 14.73,116.27 16.76,114.23 16.76,110.68 18.54,108.9 21.58,108.9 21.84,109.15 22.98,109.15 23.03,109.1 IC9.30
N$15
  Bottom 0.305: TP2.PP 16.38,115.89 17.39,114.87 17.39,111.06 18.92,109.54 21.33,109.54 21.71,109.92 23.11,109.92 23.24,109.79 23.35,109.9 IC9.31
N$18
  Bottom 0.305: TP3.PP 18.03,112.96 18.16,112.84 18.16,111.19 19.17,110.17 21.08,110.17 21.58,110.68 23.11,110.68 23.13,110.7 IC9.32
N$20
  Top 0.406: LED9_I.K 79.37,60.62 80.39,59.6 82.16,59.6 | 82.16,59.6 82.1,59.66 R25.1 | 82.16,59.6 82.29,59.47
N$21
  Bottom 0.406: 38.98,77.02 39.11,76.9 J2.4 38.98,78.55 40,79.56 D11.C
N$24
  Top 0.406: Q18.3 74.16,32.04 75.43,33.31 75.43,40.3 80.26,45.12 80.26,53.88 76.83,57.31 LED9_I.A
N$26
  Bottom 0.305: TP4.PP 19.68,113.35 18.79,112.46 18.79,111.44 19.43,110.81 20.7,110.81 21.46,111.57 23.11,111.57 23.24,111.44 23.3,111.5 IC9.33
N$27
  Bottom 0.305: TP5.PP 21.33,116.27 23.24,114.36 24.63,114.36 25.14,113.85 25.14,113.35 25.18,113.3 IC9.34
N$29
  Bottom 0.305: TP6.PP 24.25,115.12 25.14,115.12 26.03,114.23 26.03,113.47 25.9,113.35 25.94,113.3 IC9.35
N$30
  Bottom 0.305: TP7.PP 24.63,116.52 26.79,114.36 26.79,113.47 26.8,113.46 IC9.36
N$32
  Bottom 0.305: TP8.PP 26.16,116.27 27.55,114.87 27.55,113.6 27.6,113.55 IC9.37
N$46
  Top 0.61: J4.7 76.7,28.74 81.28,24.17 81.28,15.15 78.86,12.74 72.13,12.74 70.48,11.09 70.48,8.93 70.45,8.95 LED12_POWER.A
N$53
  Top 0.406: Q18.1 71.18,32.99 74.16,35.98 J4.6
N$58
  Bottom 0.406: C47.1 19.79,107.61 20.19,108.01 21.97,108.01 22.22,108.27 23.24,108.27 23.27,108.3 IC9.29
N$62  (via drill 0.6 pad 2.18)
  other vias: 91.03,90.59
N$70
  Top 0.406: LED11_OFF_ON.K 70.48,57.31 71.88,55.92 75.31,55.92 78.35,52.87 78.35,45.88 75.18,42.71 67.81,42.71 66.54,41.44 J4.3
N$71
  Top 0.406: LED11_OFF_ON.A 73.02,57.31 73.53,56.81 75.69,56.81 79.24,53.25 79.24,45.5 75.56,41.82 70.61,41.82 69.08,40.3 J4.4 69.08,37.63
N$72
  Top 0.406: Q15.3 91.1,35.98 90.8,35.98 90.8,40.55 90.42,40.93 90.42,54.27 92.32,56.17 LED10_V1.A
N$73
  Top 0.406: LED10_V1.K 94.86,62.39 95.75,63.28 107.82,63.28 108.83,62.27 108.83,59.35 109.28,58.9 | 109.28,58.9 109.34,58.84 | R21.1 109.28,58.9
N$74
  Top 0.406: R23.1 108.96,56.55 107.06,58.46 LED9_I1.K
N$75
  Top 0.61: J3.7 102.23,31.28 100.96,30.01 92.45,30.01 88.13,25.69 88.13,15.15 91.69,11.59 97.4,11.59 98.42,10.58 LED12_POWER1.A
N$76
  Top 0.406: LED9_I1.A 104.52,59.47 100.71,55.66 96.01,55.66 93.09,52.74 93.09,43.72 96.26,40.55 99.94,40.55 100.96,39.53 100.96,33.69 99.94,32.68 Q16.3
N$77
  Top 0.406: LED11_OFF_ON1.K 98.42,58.2 97.4,57.19 95.12,57.19 91.31,53.38 91.31,41.44 92.2,40.55 92.2,37.76 92.09,37.65 J3.3
N$78
  Top 0.406: LED11_OFF_ON1.A 100.96,57.82 99.56,56.42 95.63,56.42 92.2,53 92.2,42.71 94.74,40.17 94.74,37.76 94.63,37.65 J3.4
N$79
  Top 0.305: 25.59,123.44 26.92,122.36 26.92,120.71 26.54,120.33 26.54,118.81 27.68,117.66
  Top 0.406: U$7.RS 29.71,119.7 28.06,118.04 28.06,117.92 27.74,117.6 R98.1 27.68,117.66 | 25.59,123.44 R103.1
N$80
  Bottom 0.406: IC9.7 40.85,106.7 42.54,108.39 Q5.2 43.03,108.88 C35.2
N$81
  Top 0.406: LED10_V2.A 6.47,58.84 10.15,55.15 17.27,55.15 19.81,52.61 19.81,47.03 16.25,43.47 13.2,43.47 10.03,40.3 10.03,32.93 11.42,31.53 12.57,31.53 12.61,31.49 | 12.61,31.49 12.69,31.41 | 12.61,31.49 Q13.3
N$82
  Top 0.406: LED10_V2.K 9.01,62.39 9.65,63.03 18.79,63.03 19.93,61.89 19.93,58.96 21.71,57.19 R19.1
N$83
  Top 0.406: LED9_I2.K 21.2,60.62 22.09,59.73 R20.1 25.01,59.73
N$84
  Top 0.61: J6.7 24,33.95 24.38,33.56 24.38,14.51 22.22,12.36 14.47,12.36 12.57,10.45 LED12_POWER2.A
N$85
  Bottom 0.406: IC9.8 41.09,105.9 41.65,105.34 Q5.1 43.3,103.57 42.54,102.8 42.54,99.88 43.05,99.5 42.91,99.36 C36.2
N$86
  Bottom 0.406: R116.2 30.16,88.27 29.71,87.82 LED7.A
N$87
  Bottom 0.406: R117.2 27.93,88.2 27.81,88.07 27.81,86.55 27.55,86.29 LED8.A
N$88  (via drill 0.6 pad 2.18)
  other vias: 96.16,90.59
N$89
  Bottom 0.406: U$11.A 73.66,69.53 73.78,69.66 R84.2
N$90
  Top 0.406: R100.1 32,117.66 32.76,118.43 U$7.CS 32.76,128.33 31.74,129.35 27.93,129.35 24.89,126.3 23.36,126.3 20.7,123.63 20.82,123.51 R105.1
N$91
  Top 0.406: R101.1 33.97,117.6 33.78,117.79 33.78,118.3 34.28,118.81 U$7.CLK 34.28,128.59 32.63,130.24 27.55,130.24 24.51,127.19 22.22,127.19 18.66,123.63 R106.1
N$92
  Bottom 0.406: R86.2 103.37,69.78 103.25,69.91 101.72,69.91 100.96,69.15 U$13.A
N$93  (via drill 0.6 pad 1.42)
  Top 0.406: U$7.LED+ 41.91,122.24 42.41,121.73 42.41,119.95 v42.03,119.44
  Bottom 0.406: R109.2 48.45,120.65 48.51,120.58 47.37,119.44 v42.03,119.44
N$94
  Bottom 0.305: R90.1 37.84,127.51 37.84,130.87 44.7,130.87 45.97,129.6 45.97,127.95 46.48,127.44 U$8.7
  Bottom 0.406: R91.2 39.49,124.46 R90.1
N$95  (via drill 0.7 pad 1.42)
  Top 0.61: v56.26,121.85 55.88,121.35 55.88,82.36 55.37,81.85 55.37,77.4 56.26,76.52 L3.2
  Top 0.813: IC7.3 66.42,77.15 65.78,76.52 L3.2
  Bottom 0.61: C32.1 55.88,121.86 v56.26,121.85
N$96
  Bottom 0.406: LED6.A 59.05,89.47
  Bottom 0.61: 59.05,89.47 R81.2
N$97
  Top 0.406: 100.2,94.78 100.2,94.68 100.32,94.55 | B2.AC2 91.05,90.87 90.68,91.24 C30.2 | C29.2 105.28,84.9 108.45,88.07 108.45,93.91 107.56,94.8 105.53,94.8 105.51,94.78 U$6.1
  Top 0.813: B2.AC2 91.05,90.74 95.09,94.78 100.2,94.78 U$6.1 105.38,94.78 105.41,94.8
  Bottom 0.406: U$6.1 105.38,94.78
N$98  (via drill 0.6 pad 2.18)
  other vias: 91.08,85.53
N$99  (via drill 0.6 pad 2.18)
  other vias: 96.11,85.51
N$101
  Top 0.406: Q14.3 20.91,32.25 22.73,34.07 22.73,40.3 22.35,40.68 22.35,54.14 18.66,57.82 18.66,60.74 18.79,60.87 LED9_I2.A
N$103
  Top 0.406: J6.3 13.84,41.82 14.47,42.45 16.5,42.45 20.7,46.65 20.7,53 17.77,55.92 14.09,55.92 12.57,57.44 LED11_OFF_ON2.K
N$104
  Bottom 0.406: R87.2 U$14.A
N$105
  Bottom 0.406: Q6.3 53.08,113.47 53.21,113.6 D8.A 53.21,116.27 55.62,118.68 L4.2
N$106
  Bottom 0.406: D10.C 49.64,114.6 D9.A
N$107
  Bottom 0.406: D8.K 53.21,121.09 53.02,120.33 R109.1 50.35,120.65 50.41,120.58 50.41,119.19 49.25,118.03 D9.C
N$108
  Bottom 0.406: L4.1 57.4,105.98 56.64,105.22 R108.2
N$109
  Top 0.406: 96.01,85.66 B2.AC1 94.1,83.5 C26.1 | 96.13,86.88 96.06,86.88 95.6,87.34 90.37,87.34 88.84,85.81 C27.1
  Top 0.813: B2.AC1 96.13,86.88 96.13,87.06 98.85,89.77 105.23,89.77 105.28,89.72 U$6.2
N$110
  Top 0.406: C29.1 99.43,85.02 99.18,84.77 98.93,84.77 94.23,80.07 C26.2
  Top 0.61: C26.2 90.8,80.2 90.61,80.39
  Top 0.813: IC7.1 74.29,77.28 79.37,72.2 C33.+ 83.56,72.2 83.94,72.58 83.94,78.42 84.96,79.44 89.66,79.44 90.61,80.39 91.18,80.96 91.18,85.41 B2.+
N$111
  Top 0.406: R99.1 30.03,117.6 30.22,117.41 30.22,118.81 31.24,119.82 U$7.RESET 31.24,127.95 30.73,128.46 28.44,128.46 25.27,125.28 24.63,125.28 22.98,123.63 R104.1
N$113
  Top 0.406: R102.1 36.32,117.66 35.81,118.17 U$7.DAT 35.81,128.71 33.4,131.13 26.92,131.13 23.87,128.08 21.2,128.08 16.57,123.44 R107.1
N$114
  Top 0.406: LED11_OFF_ON2.A 15.11,57.57 15.87,56.81 18.28,56.81 21.58,53.5 21.58,46.39 16.38,41.18 J6.4
N$116
  Top 0.406: LED9_I3.K 50.54,59.73 R17.1
N$117
  Top 0.406: LED9_I3.A 46.73,57.19 50.29,53.63 50.29,39.91 50.8,39.41 50.8,33.31 49.52,32.04 Q12.3
N$118
  Top 0.406: Q12.1 47.17,32.99 49.52,35.34 J8.6
N$119
  Top 0.61: J8.7 52.06,15.53 49.65,13.12 43.3,13.12 40.63,10.45 LED12_POWER3.A
N$120
  Bottom 0.406: U$15.A 43.68,69.4 43.94,69.66 R88.2
N$121
  Top 0.406: J8.5 46.98,36.1 45.21,34.33 45.21,32.29 43.94,31.02 43.43,31.02 43.36,31.09 Q11.1
N$122
  Top 0.406: J8.3 41.91,42.07 42.41,42.58 44.95,42.58 48.51,46.14 48.51,52.61 45.33,55.79 42.67,55.79 40.63,57.82 LED11_OFF_ON3.K
N$123
  Top 0.406: LED11_OFF_ON3.A 43.17,57.19 43.68,56.68 45.97,56.68 49.4,53.25 49.4,45.76 44.44,40.8 J8.4
N$127  (via drill 3.2 pad 4)  (1 unrouted)
  other vias: 110.99,130.24 110.74,9.08
N$129
  Top 0.406: J8.2 39.36,35.34 41.4,33.31 42.92,33.31 43.17,33.06 | 43.26,32.97 43.43,32.8 | 43.26,32.97 Q11.2 43.24,32.99 43.17,33.06 | 43.26,32.97 43.17,33.06 | Q12.2 47.16,30.43 46.48,29.75 42.92,29.75 42.16,30.52 42.16,32.04 43.17,33.06
N$130  (via drill 0.6 pad 1.42, 0.7 pad 1.42)
  Top 0.406: BPT-14X.2 v11.81,77.28
  Top 0.61: BPT-14X.2 10.15,88.33 v11.42,89.6
  Bottom 0.406: BPT-14X.2 10.03,79.06 | L5.1 13.2,66.48 11.17,68.51 11.17,69.4 11.81,70.04 v11.81,77.28
  Bottom 0.61: T8.3 v11.42,89.6
N$131
  Top 0.406: LED10_V3.A 34.54,59.47 39.11,54.9 44.7,54.9 47.49,52.11 47.49,46.52 44.44,43.47 41.65,43.47 38.09,39.91 38.09,33.56 39.62,32.04 Q11.3 | Q11.3 41.14,32.04 | Q11.3 41.4,32.04
N$132
  Top 0.406: LED10_V3.K 37.08,61.25 38.6,62.77 47.24,62.77 48,62.01 48,58.46 49.02,57.44 R16.1
N$133
  Top 0.406: Q14.1 18.71,32.25 18.66,32.29 21.46,35.09 J6.6
N$134
  Top 0.406: J6.5 18.92,35.6 16.5,33.18 16.5,32.29 14.81,30.6 Q13.1
N$135
  Top 0.406: J6.2 11.3,35.85 14.73,32.42 14.79,32.48 Q13.2 14.81,32.46 14.85,32.42 13.71,31.28 13.71,28.87 17.77,28.87 18.71,29.8 Q14.2
N$136
  Top 0.406: Q16.1 97.6,33.63 97.66,33.56 99.69,35.6 J3.6
N$137
  Top 0.406: Q15.1 94.68,32.23 95.88,33.44 95.88,34.71 97.15,35.98 J3.5
N$138
  Top 0.406: Q16.2 97.47,31.73 97.4,31.79 96.77,31.15 92.32,31.15 | 92.32,31.15 92.2,31.15 92.2,33.18 93.15,34.13 Q15.2 | J3.2 89.53,31.15 92.32,31.15
N$139
  Top 0.406: J4.5 71.62,36.74 68.96,34.07 68.96,33.31 66.88,31.24 Q17.1
N$140
  Top 0.406: J4.2 64,35.85 66.8,33.06 66.86,33.12 Q17.2 66.88,33.14 | Q18.2 71.16,29.37 65.78,29.37 65.78,31.91 66.88,33.14 | 66.88,33.14 66.92,33.18
N$141
  Top 0.406: LED10_V.A 64.44,60.95 70.35,55.03 74.42,55.03 77.34,52.11 77.34,46.39 74.67,43.72 64.89,43.72 62.73,41.57 62.73,32.29 62.86,32.17 Q17.3 64.89,32.17
N$151
  Bottom 0.406: R79.1 70.54,115.19 70.86,114.87 72.64,114.87 72.77,115 R77.2 73.34,115.19 73.72,114.55 75.31,112.96 81.4,112.96 82.55,111.82 82.55,111.19 | 82.55,111.19 U$5.A.A | 82.55,111.19 U$5.A
N$152
  Bottom 0.406: R78.1 67.18,115.12 67.81,115.12 68.57,114.36 68.57,113.73 69.46,112.84 71.88,112.84 72.51,112.2 72.51,110.42 73.53,109.41 76.19,109.41 77.97,111.19 U$5.B U$5.B.B | R78.1 68.32,115.25 68.19,115.12 67.75,114.81 | R78.1 67.81,115 67.68,114.87 R80.1
PIK  (via drill 0.7 pad 1.42)
  Top 0.406: v11.3,100.26 11.3,99.25 12.82,97.72 29.33,97.72 30.22,96.84 v30.22,94.42
  Bottom 0.406: IC9.16 30,99.59 30.22,99.38 v30.22,94.42 | R118.2 10.47,95.12 10.41,95.06 10.45,95.01 T8.1 10.47,99.44 v11.3,100.26
PWM_LCD  (via drill 0.7 pad 1.42)
  Top 0.406: v32.89,97.72 31.49,99.12 31.49,104.71 32.51,105.73 40,105.73 40.63,105.09 40.63,97.72 v41.78,96.58
  Bottom 0.406: Q6.1 54.56,111.23 55.11,110.68 55.11,109.28 R111.1 52.63,109.09 52.7,109.03 51.56,107.88 49.91,107.88 48.25,106.23 48.25,99.38 45.46,96.58 v41.78,96.58 | IC9.14 31.6,99.01 v32.89,97.72
RESET_LCD  (via drill 0.6 pad 1.42)
  Top 0.406: R104.2 v22.98,119.82 R97.1
  Bottom 0.406: v22.98,119.82 24.25,121.09 32,121.09 33.4,119.7 33.4,115.5 32.38,114.49 32.38,113.6 32.41,113.57 IC9.43
RS_LCD  (via drill 0.6 pad 1.42)
  Top 0.406: R103.2 v25.27,119.95 R96.1
  Bottom 0.406: v25.27,119.95 26.66,118.55 31.62,118.55 31.62,116.01 30.86,115.25 30.86,113.47 30.8,113.42 IC9.41 30.86,113.25 30.86,113.22
RST_G
  Bottom 0.406: IC9.4 36.39,109.1 38.73,111.44 38.73,115.5 | 40.89,115.5 41.02,115.5 41.08,115.44 R113.1 40.89,115.5 | 38.73,115.5 40.89,115.5 | 38.73,115.5 38.73,121.6 35.68,124.65 16.12,124.65 13.96,122.49 13.96,121.09 13.71,120.84 SV3.5
RXD_G  (via drill 0.7 pad 1.42)
  Top 0.406: v38.86,104.46 38.86,85.41 34.41,80.96 29.97,80.96 v29.71,80.71 27.55,78.55 J11.3
  Bottom 0.305: IC9.9 38.21,105.1 v38.86,104.46
  Bottom 0.406: LED7.C v29.71,80.71 30.22,81.21 IC10.1
S$2  (via drill 3.2 pad 4)
  other vias: 110.74,3.74
S$3  (via drill 3.2 pad 4)  (2 unrouted)
  other vias: 3.17,3.62 3.04,8.95 2.79,55.94
SCK_G  (via drill 0.6 pad 1.42)
  Top 0.406: R94.1 v18.66,119.82 R106.2
  Bottom 0.406: IC9.3 36.18,109.9 37.84,111.57 37.84,120.84 35.05,123.76 17.14,123.76 14.98,121.6 14.98,119.57 | 14.98,119.57 14.98,119.06 15.74,118.43 17.27,118.43 v18.66,119.82 | SV3.1 10.15,110.68 9.39,111.44 9.39,118.43 10.54,119.57 14.98,119.57
SCL
  Bottom 0.305: IC9.19 27.6,100.06 26.03,98.49 23.62,98.49 22.35,97.22 IC8.6
  Bottom 0.406: R82.2 20.25,90.81 22.35,92.9 IC8.6
SDA
  Bottom 0.406: IC9.20 26.8,100.4 25.65,99.25 23.24,99.25 21.08,97.09 21.08,94.68 20.98,94.58 | 20.98,94.58 20.95,94.55 | 20.98,94.58 IC8.5 21.05,94.58 20.95,94.68 20.89,94.62 R83.2
TXD_G  (via drill 0.7 pad 1.42)
  Top 0.406: v37.71,103.19 37.71,86.42 33.78,82.48 27.93,82.48 27.3,81.85 v27.3,80.71 26.03,80.71 25.01,79.69 J11.2 24.89,76.77
  Bottom 0.406: IC9.10 37.23,104.3 37.59,103.95 37.59,103.31 v37.71,103.19 | v27.3,80.71 27.68,80.71 27.68,82.61 27.65,82.61 LED8.C 27.55,82.74 28.95,84.14 30.22,84.14 31.11,85.02 IC10.4
(copper drawn outside any net)
  shapes: Top area x8

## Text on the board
Top: -
Bottom: - | - | - | + | + | + | +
